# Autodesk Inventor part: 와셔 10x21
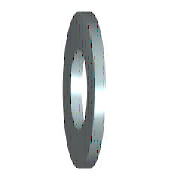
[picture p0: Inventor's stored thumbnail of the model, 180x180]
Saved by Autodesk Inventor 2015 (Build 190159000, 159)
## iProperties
Created: 2012-02
Part Number: 와셔 10x21
Material: 강철, 연강
Description: 평면 와셔
Document SubType Name: Modeling
Standard: KS B 1326
Designer: mduedu
Standards Organization: KS
Language: ko-KR
Size Designation: 10x21
Categories: <MemberInstance><Categories><Category DisplayName="조임쇠" InternalName="e4da775c-781d-43d5-af7c-5136215cf5a6" Mnemonic="FSTN"><Category DisplayName="와셔" InternalN
Density: 1 g/cm^3
Appearance: 파란색 - 벽 페인트 - 광택
IsCustomPart: 1
Author: mduedu
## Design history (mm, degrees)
sketch "스케치"
  geometry: C1 r 10.5 at (0, 0); C2 r 5.25 at (0, 0); 1 further point
  constraints: 2 centre point, 2 coincident
  dimensions: "d0" = 10.5 diameter of C2 (= SD1); "d1" = 21 diameter of C1 (= SD2)
extrude "본체" new body sketch "스케치" distance "d2" = 2 (= SD); taper "d3" = 0 deg
workaxis "Work Axis1"
workplane "Work Plane1"
body "Solid1"
other parameters: "SD1" = 10.5 [user parameter; used in 1 equation term], "SD2" = 21 [user parameter; used in 1 equation term], "SD" = 2 [user parameter; used in 1 equation term], "d4" = 0, "d5" = 0, "d6" = 0, "d7" = 0
